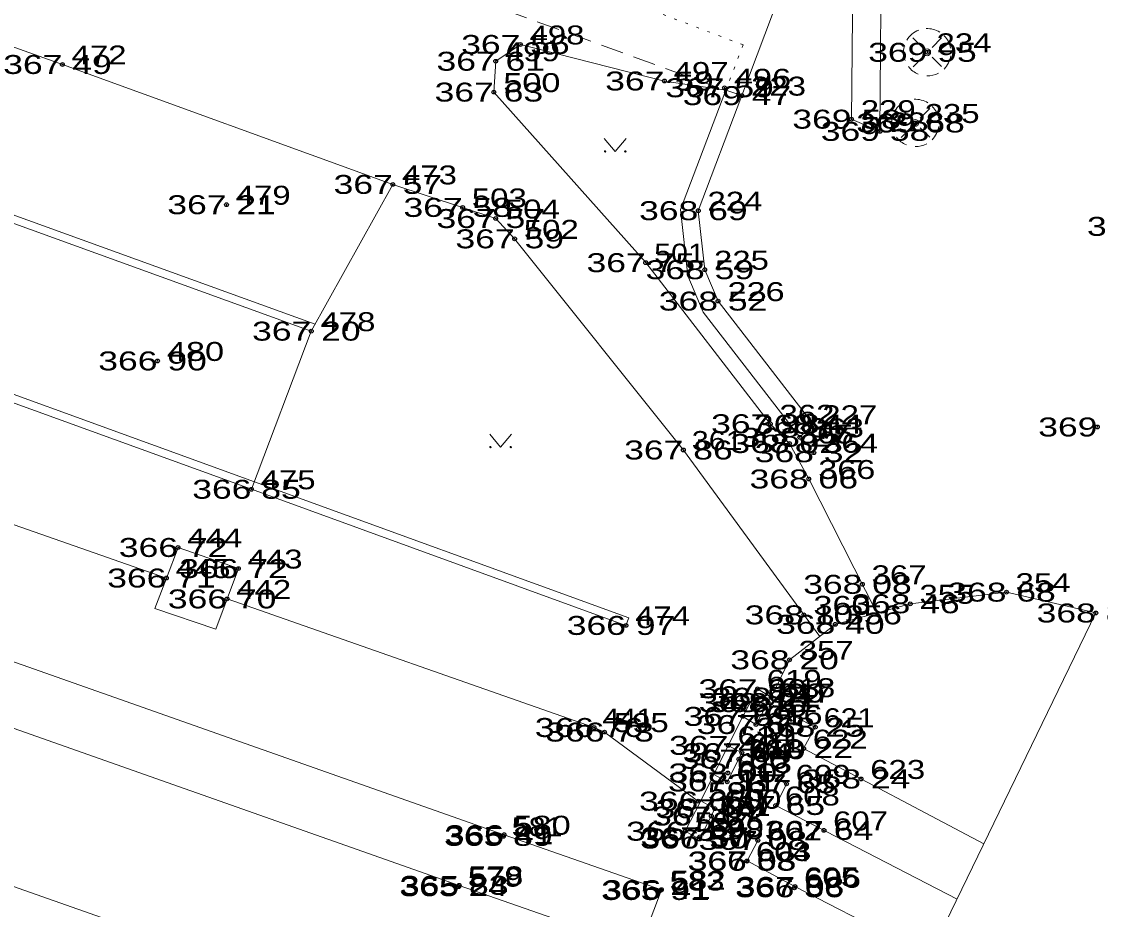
# Model space of a CAD drawing. Extents: x -789669 to -789458, y -977587 to -977420.
# Drawn here: x -789569.11 to -789529.27, y -977530.34 to -977497.54 of the extents above; entities that cross this region are included whole.
import ezdxf
from ezdxf.enums import TextEntityAlignment as Align

# ---------------------------------------------------------------- set-up
doc = ezdxf.new("R2010")
doc.units = 0
doc.header["$LTSCALE"] = 0.28
doc.header["$PDMODE"] = 32
doc.header["$PDSIZE"] = 0.14
doc.linetypes.add('DOTTED', pattern=[1.5, 0.3, -1.2])
doc.linetypes.add('MEDIUM_DASHED', pattern=[4.5, 3, -1.5])
for name, color, linetype, lineweight in [('1', 7, 'Continuous', 13), ('3', 7, 'Continuous', 13), ('4', 7, 'Continuous', 13), ('9', 7, 'Continuous', 25)]:
    doc.layers.add(name, color=color, linetype=linetype, lineweight=lineweight)
for name, color, linetype in [('57', 7, 'Continuous'), ('58', 7, 'Continuous'), ('59', 7, 'Continuous')]:
    doc.layers.add(name, color=color, linetype=linetype)

msp = doc.modelspace()

# ---------------------------------------------------------------- linework, layer by layer
at = {"layer": '1'}
for p, q in [((-789544.67, -977513.37), (-789539.637, -977520.257)), ((-789563.76, -977518.1), (-789563.33, -977516.97)), ((-789563.33, -977516.97), (-789561.1, -977517.75)), ((-789564.19, -977519.23), (-789563.76, -977518.1)), ((-789561.52, -977518.87), (-789561.1, -977517.75)), ((-789561.94, -977519.99), (-789561.52, -977518.87)), ((-789561.52, -977518.87), (-789547.97, -977523.62)), ((-789564.19, -977519.23), (-789561.94, -977519.99)), ((-789546.79, -977519.85), (-789546.68, -977519.57)), ((-789543.01, -977524.28), (-789543.55, -977525.36)), ((-789544.6, -977527.45), (-789544.03, -977526.33)), ((-789543.51, -977526.62), (-789544.03, -977526.33)), ((-789552.95, -977529.45), (-789548.4, -977531.05))]:
    msp.add_line(p, q, dxfattribs=at)
for points in [[(-789555.4, -977503.56), (-789567.6, -977499.13), (-789583.03, -977493.61), (-789593.57, -977489.74)], [(-789593.53, -977495.98), (-789573.48, -977503.22), (-789558.267, -977508.722)], [(-789593.53, -977496.29), (-789573.48, -977503.53), (-789558.41, -977508.98)], [(-789541.46, -977512.4), (-789546.06, -977506.45), (-789551.67, -977500.15), (-789551.6, -977499.01), (-789550.69, -977498.39), (-789545.37, -977499.74), (-789543.101, -977500.084)], [(-789594.9, -977502.08), (-789575.7, -977509.03), (-789560.51, -977514.54), (-789546.68, -977519.57)], [(-789595.01, -977502.36), (-789575.81, -977509.31), (-789560.62, -977514.82), (-789546.79, -977519.85)], [(-789560.62, -977514.82), (-789558.41, -977508.98), (-789555.4, -977503.56)], [(-789544.67, -977513.37), (-789550.9, -977505.57), (-789551.6, -977504.82), (-789552.82, -977504.41), (-789555.4, -977503.56)], [(-789596.21, -977506.78), (-789579.37, -977512.64), (-789563.76, -977518.1)], [(-789597.58, -977510.24), (-789597.92, -977511.15), (-789592.62, -977513.01), (-789551.29, -977527.58)], [(-789541.46, -977512.4), (-789540.75, -977513.13), (-789540.04, -977514.44), (-789537.522, -977519.388)], [(-789552.95, -977529.45), (-789592.39, -977515.54), (-789598.63, -977513.34)], [(-789529.44, -977519.39), (-789532.74, -977518.62), (-789536.29, -977519.05), (-789539.06, -977519.81), (-789540.75, -977521.12), (-789541.43, -977522.5)], [(-789529.44, -977519.39), (-789535.58, -977532.06), (-789534.02, -977534.68), (-789533.48, -977537.08), (-789533.87, -977537.97), (-789534.65, -977538.75)], [(-789541.54, -977522.7), (-789539.8, -977523.61), (-789540.23, -977524.4), (-789533.572, -977527.917)], [(-789542.48, -977523.21), (-789543.01, -977524.28), (-789542.51, -977524.55), (-789543.05, -977525.63)], [(-789547.97, -977523.62), (-789547.58, -977523.79), (-789544.058, -977526.386)], [(-789542.62, -977524.79), (-789540.86, -977525.7), (-789541.26, -977526.5), (-789534.563, -977529.962)], [(-789543.05, -977525.63), (-789543.55, -977525.36), (-789544.03, -977526.33)], [(-789544.6, -977527.45), (-789544.08, -977527.74), (-789543.51, -977526.62)], [(-789543.64, -977526.89), (-789541.92, -977527.79), (-789542.32, -977528.55), (-789540.55, -977529.49), (-789535.58, -977532.06)], [(-789549.38, -977540.36), (-789548.06, -977536.86), (-789546.98, -977533.84), (-789546.17, -977534.14), (-789545.48, -977532.28), (-789546.37, -977531.97), (-789545.48, -977529.61), (-789551.29, -977527.58)]]:
    msp.add_lwpolyline(points, dxfattribs=at)
for points in [[(-789538.06, -977493.8), (-789538.4, -977494.8), (-789538.46, -977501.15), (-789537.41, -977501.6), (-789537.35, -977494.03)], [(-789610.77, -977541.45), (-789601.76, -977516.24), (-789599.84, -977516.93), (-789600.42, -977518.57), (-789557, -977533.86), (-789556.41, -977532.23), (-789554.54, -977532.86), (-789563.4, -977558.1)], [(-789541.93, -977522.19), (-789541.43, -977522.5), (-789541.99, -977523.51), (-789542.48, -977523.21)]]:
    msp.add_lwpolyline(points, close=True, dxfattribs=at)
at = {"layer": '3'}
for p, q in [((-789542.51, -977500.28), (-789543.101, -977500.084)), ((-789539.88, -977512.42), (-789540.37, -977512.9))]:
    msp.add_line(p, q, dxfattribs=at)
for points in [[(-789543.54, -977490.46), (-789539.4, -977492), (-789542.51, -977500.28)], [(-789540.37, -977512.9), (-789543.936, -977508.278), (-789544.501, -977506.94), (-789544.77, -977504.491), (-789543.101, -977500.084)], [(-789539.88, -977512.42), (-789543.39, -977507.87), (-789543.88, -977506.71), (-789544.12, -977504.53), (-789542.51, -977500.28)]]:
    msp.add_lwpolyline(points, dxfattribs=at)
at = {"layer": '4'}
for p, q in [((-789536.194, -977498.142), (-789535.837, -977498.498)), ((-789535.134, -977498.15), (-789535.487, -977498.503)), ((-789536.19, -977499.213), (-789535.838, -977498.862)), ((-789535.66, -977498.686), (-789535.66, -977498.674)), ((-789535.486, -977498.857), (-789535.134, -977499.207)), ((-789536.634, -977500.752), (-789536.277, -977501.108)), ((-789535.574, -977500.76), (-789535.927, -977501.113)), ((-789536.1, -977501.296), (-789536.1, -977501.284)), ((-789536.63, -977501.823), (-789536.278, -977501.472)), ((-789535.926, -977501.467), (-789535.574, -977501.817))]:
    msp.add_line(p, q, dxfattribs=at)
for points in [[(-789547.59, -977501.863), (-789547.188, -977502.342), (-789546.786, -977501.863)], [(-789547.562, -977502.319), (-789547.548, -977502.327), (-789547.543, -977502.342), (-789547.549, -977502.355), (-789547.562, -977502.363), (-789547.578, -977502.355), (-789547.584, -977502.342), (-789547.58, -977502.328), (-789547.569, -977502.322), (-789547.554, -977502.328), (-789547.549, -977502.342), (-789547.552, -977502.352), (-789547.562, -977502.357), (-789547.573, -977502.352), (-789547.579, -977502.341), (-789547.574, -977502.331), (-789547.569, -977502.328), (-789547.558, -977502.332), (-789547.553, -977502.342), (-789547.559, -977502.349), (-789547.567, -977502.347), (-789547.572, -977502.339), (-789547.567, -977502.334), (-789547.559, -977502.338), (-789547.562, -977502.342)], [(-789546.812, -977502.32), (-789546.798, -977502.328), (-789546.793, -977502.343), (-789546.799, -977502.356), (-789546.812, -977502.364), (-789546.828, -977502.356), (-789546.834, -977502.343), (-789546.83, -977502.329), (-789546.819, -977502.323), (-789546.804, -977502.329), (-789546.799, -977502.343), (-789546.802, -977502.353), (-789546.812, -977502.358), (-789546.823, -977502.353), (-789546.829, -977502.342), (-789546.824, -977502.332), (-789546.819, -977502.329), (-789546.808, -977502.333), (-789546.803, -977502.343), (-789546.809, -977502.35), (-789546.817, -977502.348), (-789546.822, -977502.34), (-789546.817, -977502.335), (-789546.809, -977502.339), (-789546.812, -977502.343)], [(-789551.82, -977512.782), (-789551.418, -977513.261), (-789551.016, -977512.782)], [(-789551.792, -977513.238), (-789551.778, -977513.246), (-789551.773, -977513.261), (-789551.779, -977513.274), (-789551.792, -977513.282), (-789551.808, -977513.274), (-789551.814, -977513.261), (-789551.81, -977513.247), (-789551.799, -977513.241), (-789551.784, -977513.247), (-789551.779, -977513.261), (-789551.782, -977513.271), (-789551.792, -977513.276), (-789551.803, -977513.271), (-789551.809, -977513.26), (-789551.804, -977513.25), (-789551.799, -977513.247), (-789551.788, -977513.251), (-789551.783, -977513.261), (-789551.789, -977513.268), (-789551.797, -977513.266), (-789551.802, -977513.258), (-789551.797, -977513.253), (-789551.789, -977513.257), (-789551.792, -977513.261)], [(-789551.042, -977513.239), (-789551.028, -977513.247), (-789551.023, -977513.262), (-789551.029, -977513.275), (-789551.042, -977513.283), (-789551.058, -977513.275), (-789551.064, -977513.262), (-789551.06, -977513.248), (-789551.049, -977513.242), (-789551.034, -977513.248), (-789551.029, -977513.262), (-789551.032, -977513.272), (-789551.042, -977513.277), (-789551.053, -977513.272), (-789551.059, -977513.261), (-789551.054, -977513.251), (-789551.049, -977513.248), (-789551.038, -977513.252), (-789551.033, -977513.262), (-789551.039, -977513.269), (-789551.047, -977513.267), (-789551.052, -977513.259), (-789551.047, -977513.254), (-789551.039, -977513.258), (-789551.042, -977513.262)]]:
    msp.add_lwpolyline(points, dxfattribs=at)
for centre, radius in [((-789535.6639, -977498.6794), 0.125), ((-789536.1039, -977501.2894), 0.125), ((-789547.563, -977502.342), 0.025), ((-789546.813, -977502.342), 0.025), ((-789551.793, -977513.261), 0.025), ((-789551.043, -977513.261), 0.025)]:
    msp.add_circle(centre, radius, dxfattribs=at)
for centre, start, end in [((-789535.6639, -977498.6794), 111.04924, 149.34666), ((-789535.6639, -977498.6794), 57.94289, 92.85253), ((-789535.6639, -977498.6794), 9.68453, 44.47714), ((-789535.6639, -977498.6794), 166.76695, 200.11735), ((-789535.6639, -977498.6794), 315.09105, 351.67435), ((-789535.6639, -977498.6794), 217.06959, 247.69959), ((-789535.6639, -977498.6794), 269.18965, 298.56841), ((-789536.1039, -977501.2894), 111.04924, 149.34666), ((-789536.1039, -977501.2894), 57.94289, 92.85253), ((-789536.1039, -977501.2894), 9.68453, 44.47714), ((-789536.1039, -977501.2894), 166.76695, 200.11735), ((-789536.1039, -977501.2894), 315.09105, 351.67435), ((-789536.1039, -977501.2894), 217.06959, 247.69959), ((-789536.1039, -977501.2894), 269.18965, 298.56841)]:
    msp.add_arc(centre, 0.875, start, end, dxfattribs=at)
at = {"layer": '57'}
for p in [(-789550.69, -977498.39), (-789551.6, -977499.01), (-789535.66, -977498.68), (-789567.6, -977499.13), (-789545.37, -977499.74), (-789551.67, -977500.15), (-789543.15, -977499.99), (-789542.51, -977500.28), (-789538.46, -977501.15), (-789536.1, -977501.29), (-789537.41, -977501.6), (-789555.4, -977503.56), (-789561.54, -977504.31), (-789552.82, -977504.41), (-789544.12, -977504.53), (-789551.6, -977504.82), (-789550.9, -977505.57), (-789546.06, -977506.45), (-789543.88, -977506.71), (-789543.39, -977507.87), (-789558.41, -977508.98), (-789564.09, -977510.08), (-789541.46, -977512.4), (-789539.88, -977512.42), (-789529.38, -977512.52), (-789540.37, -977512.9), (-789544.67, -977513.37), (-789540.75, -977513.13), (-789539.85, -977513.47), (-789540.04, -977514.44), (-789560.62, -977514.82), (-789563.33, -977516.97), (-789561.1, -977517.75), (-789563.76, -977518.1), (-789538.06, -977518.33), (-789561.52, -977518.87), (-789532.74, -977518.62), (-789536.29, -977519.05), (-789540.22, -977519.46), (-789529.44, -977519.39), (-789546.79, -977519.85), (-789539.06, -977519.81), (-789540.75, -977521.12), (-789541.93, -977522.19), (-789541.43, -977522.5), (-789541.92, -977522.7), (-789541.54, -977522.7), (-789542.48, -977523.21), (-789547.97, -977523.62), (-789541.99, -977523.51), (-789539.8, -977523.61), (-789547.58, -977523.79), (-789543.01, -977524.28), (-789542.51, -977524.55), (-789540.23, -977524.4), (-789542.62, -977524.79), (-789543.03, -977525.3), (-789543.05, -977525.63), (-789540.86, -977525.7), (-789538.11, -977525.52), (-789544.12, -977526.34), (-789541.26, -977526.5), (-789543.64, -977526.89), (-789543.51, -977526.62), (-789551.32, -977527.64), (-789551.29, -977527.58), (-789544.6, -977527.45), (-789544.08, -977527.74), (-789544.06, -977527.66), (-789539.48, -977527.42), (-789541.92, -977527.79), (-789542.33, -977528.56), (-789542.32, -977528.55), (-789552.97, -977529.5), (-789552.95, -977529.45), (-789545.52, -977529.64), (-789545.48, -977529.61), (-789540.57, -977529.54), (-789540.55, -977529.49)]:
    msp.add_point(p, dxfattribs=at)
at = {"layer": '9', "linetype": 'MEDIUM_DASHED', "lineweight": 13}
msp.add_line((-789597.427, -977480.319), (-789543.101, -977500.084), dxfattribs=at)
at = {"layer": '9', "linetype": 'DOTTED', "lineweight": 13}
for q in [(-789546.04, -977497.05), (-789543.101, -977500.084)]:
    msp.add_line((-789542.465, -977498.406), q, dxfattribs=at)

# ---------------------------------------------------------------- texts
at = {"layer": '58'}
for s, width, p in [(' 498', 1.3, (-789550.69, -977498.39)), (' 234', 1.3, (-789535.66, -977498.68)), (' 472', 1.3, (-789567.6, -977499.13)), (' 499', 1.3, (-789551.6, -977499.01)), (' 497', 1.3, (-789545.37, -977499.74)), (' 496', 1.35, (-789543.15, -977499.99)), (' 500', 1.35, (-789551.67, -977500.15)), (' 223', 1.3, (-789542.51, -977500.28)), (' 229', 1.3, (-789538.46, -977501.15)), (' 235', 1.3, (-789536.1, -977501.29)), (' 228', 1.3, (-789537.41, -977501.6)), (' 473', 1.3, (-789555.4, -977503.56)), (' 479', 1.3, (-789561.54, -977504.31)), (' 503', 1.3, (-789552.82, -977504.41)), (' 504', 1.3, (-789551.6, -977504.82)), (' 224', 1.3, (-789544.12, -977504.53)), (' 502', 1.3, (-789550.9, -977505.57)), (' 501', 1.2, (-789546.06, -977506.45)), (' 225', 1.3, (-789543.88, -977506.71)), (' 226', 1.35, (-789543.39, -977507.87)), (' 478', 1.3, (-789558.41, -977508.98)), (' 480', 1.35, (-789564.09, -977510.08)), (' 362', 1.3, (-789541.46, -977512.4)), (' 227', 1.3, (-789539.88, -977512.42)), (' 365', 1.3, (-789540.75, -977513.13)), (' 363', 1.3, (-789540.37, -977512.9)), (' 361', 1.2, (-789544.67, -977513.37)), (' 364', 1.3, (-789539.85, -977513.47)), (' 366', 1.35, (-789540.04, -977514.44)), (' 475', 1.3, (-789560.62, -977514.82)), (' 444', 1.3, (-789563.33, -977516.97)), (' 443', 1.3, (-789561.1, -977517.75)), (' 445', 1.3, (-789563.76, -977518.1)), (' 367', 1.3, (-789538.06, -977518.33)), (' 354', 1.3, (-789532.74, -977518.62)), (' 442', 1.3, (-789561.52, -977518.87)), (' 355', 1.3, (-789536.29, -977519.05)), (' 360', 1.35, (-789540.22, -977519.46)), (' 474', 1.3, (-789546.79, -977519.85)), (' 356', 1.35, (-789539.06, -977519.81)), (' 357', 1.3, (-789540.75, -977521.12)), (' 619', 1.3, (-789541.93, -977522.19)), (' 620', 1.35, (-789541.92, -977522.7)), (' 617', 1.3, (-789541.54, -977522.7)), (' 618', 1.3, (-789541.43, -977522.5)), (' 615', 1.3, (-789542.48, -977523.21)), (' 616', 1.35, (-789541.99, -977523.51)), (' 621', 1.2, (-789539.8, -977523.61)), (' 441', 1.2, (-789547.97, -977523.62)), (' 595', 1.3, (-789547.58, -977523.79)), (' 614', 1.3, (-789543.01, -977524.28)), (' 622', 1.3, (-789540.23, -977524.4)), (' 610', 1.35, (-789542.62, -977524.79)), (' 611', 1.2, (-789542.51, -977524.55)), (' 613', 1.3, (-789543.03, -977525.3)), (' 623', 1.3, (-789538.11, -977525.52)), (' 612', 1.3, (-789543.05, -977525.63)), (' 609', 1.3, (-789540.86, -977525.7)), (' 596', 1.35, (-789544.12, -977526.34)), (' 600', 1.35, (-789543.51, -977526.62)), (' 608', 1.3, (-789541.26, -977526.5)), (' 601', 1.2, (-789543.64, -977526.89)), (' 580', 1.35, (-789551.29, -977527.58)), (' 597', 1.3, (-789544.6, -977527.45)), (' 607', 1.3, (-789539.48, -977527.42)), (' 581', 1.2, (-789551.32, -977527.64)), (' 598', 1.3, (-789544.08, -977527.74)), (' 599', 1.3, (-789544.06, -977527.66)), (' 602', 1.3, (-789541.92, -977527.79)), (' 604', 1.3, (-789542.33, -977528.56)), (' 603', 1.3, (-789542.32, -977528.55)), (' 579', 1.3, (-789552.97, -977529.5)), (' 578', 1.3, (-789552.95, -977529.45)), (' 606', 1.35, (-789540.57, -977529.54)), (' 605', 1.3, (-789540.55, -977529.49)), (' 583', 1.3, (-789545.52, -977529.64)), (' 582', 1.3, (-789545.48, -977529.61))]:
    msp.add_text(s, height=0.7, dxfattribs=dict(at, width=width)).set_placement(p)
at = {"layer": '59', "width": 1.4}
for s, p in [('367 56 ', (-789550.69, -977498.74)), ('369 95 ', (-789535.66, -977499.03)), ('367 49 ', (-789567.6, -977499.48)), ('367 61 ', (-789551.6, -977499.36)), ('367 59 ', (-789545.37, -977500.09)), ('367 63 ', (-789551.67, -977500.5)), ('367 59 ', (-789543.15, -977500.34)), ('369 47 ', (-789542.51, -977500.63)), ('369 58 ', (-789538.46, -977501.5)), ('369 68 ', (-789536.1, -977501.64)), ('369 58 ', (-789537.41, -977501.95)), ('367 57 ', (-789555.4, -977503.91)), ('367 21 ', (-789561.54, -977504.66)), ('367 58 ', (-789552.82, -977504.76)), ('368 69 ', (-789544.12, -977504.88)), ('367 57 ', (-789551.6, -977505.17)), ('370 12 ', (-789527.58, -977505.46)), ('367 59 ', (-789550.9, -977505.92)), ('367 75 ', (-789546.06, -977506.8)), ('368 59 ', (-789543.88, -977507.06)), ('368 52 ', (-789543.39, -977508.22)), ('367 20 ', (-789558.41, -977509.33)), ('366 90 ', (-789564.09, -977510.43)), ('367 98 ', (-789541.46, -977512.75)), ('368 44 ', (-789539.88, -977512.77)), ('368 27 ', (-789540.37, -977513.25)), ('369 34 ', (-789529.38, -977512.87)), ('368 02 ', (-789540.75, -977513.48)), ('367 86 ', (-789544.67, -977513.72)), ('368 32 ', (-789539.85, -977513.82)), ('368 06 ', (-789540.04, -977514.79)), ('366 85 ', (-789560.62, -977515.17)), ('366 72 ', (-789563.33, -977517.32)), ('366 72 ', (-789561.1, -977518.1)), ('366 71 ', (-789563.76, -977518.45)), ('368 08 ', (-789538.06, -977518.68)), ('366 70 ', (-789561.52, -977519.22)), ('368 68 ', (-789532.74, -977518.97)), ('368 46 ', (-789536.29, -977519.4)), ('368 10 ', (-789540.22, -977519.81)), ('368 86 ', (-789529.44, -977519.74)), ('366 97 ', (-789546.79, -977520.2)), ('368 40 ', (-789539.06, -977520.16)), ('368 20 ', (-789540.75, -977521.47)), ('367 90 ', (-789541.93, -977522.54)), ('368 46 ', (-789541.92, -977523.05)), ('368 21 ', (-789541.54, -977523.05)), ('368 22 ', (-789541.43, -977522.85)), ('367 69 ', (-789542.48, -977523.56)), ('366 76 ', (-789547.97, -977523.97)), ('367 63 ', (-789541.99, -977523.86)), ('368 25 ', (-789539.8, -977523.96)), ('366 73 ', (-789547.58, -977524.14)), ('367 43 ', (-789543.01, -977524.63)), ('368 22 ', (-789540.23, -977524.75)), ('367 66 ', (-789542.62, -977525.14)), ('367 64 ', (-789542.51, -977524.9)), ('367 11 ', (-789543.05, -977525.98)), ('368 00 ', (-789543.03, -977525.65)), ('368 24 ', (-789538.11, -977525.87)), ('367 65 ', (-789540.86, -977526.05)), ('366 65 ', (-789544.12, -977526.69)), ('367 09 ', (-789543.51, -977526.97)), ('367 65 ', (-789541.26, -977526.85)), ('367 07 ', (-789543.64, -977527.24)), ('365 89 ', (-789551.32, -977527.99)), ('366 41 ', (-789551.29, -977527.93)), ('366 53 ', (-789544.6, -977527.8)), ('367 64 ', (-789539.48, -977527.77)), ('366 50 ', (-789544.08, -977528.09)), ('367 37 ', (-789544.06, -977528.01)), ('367 08 ', (-789541.92, -977528.14)), ('366 53 ', (-789542.33, -977528.91)), ('367 08 ', (-789542.32, -977528.9)), ('365 24 ', (-789552.97, -977529.85)), ('365 83 ', (-789552.95, -977529.8)), ('366 41 ', (-789545.48, -977529.96)), ('366 56 ', (-789540.57, -977529.89)), ('367 08 ', (-789540.55, -977529.84)), ('365 91 ', (-789545.52, -977529.99))]:
    msp.add_text(s, height=0.7, dxfattribs=at).set_placement(p, align=Align.CENTER)

doc.saveas('drawing.dxf')
